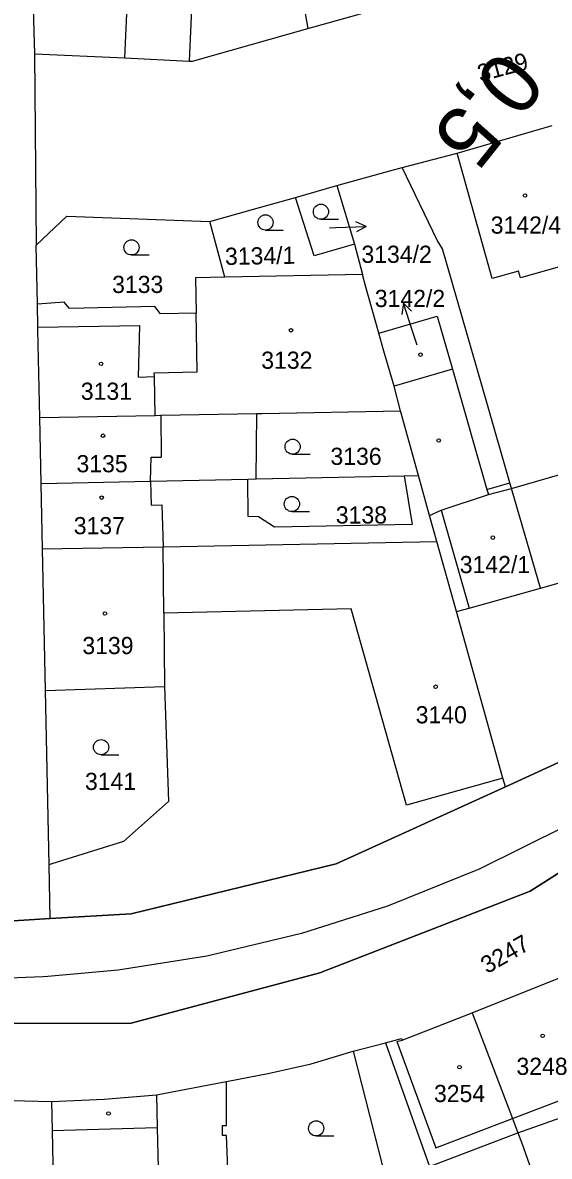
# Model space of a CAD drawing. Extents: x -738085 to -734306, y -1122197 to -1119753.
# Drawn here: x -734573.1 to -734521, y -1120242.7 to -1120130.5 of the extents above; entities that cross this region are included whole.
import ezdxf

# ---------------------------------------------------------------- set-up
doc = ezdxf.new("R2010")
doc.units = 0
for name, color, linetype in [('Hranice parcel', 7, 'Continuous'), ('Parcelní čísla', 7, 'Continuous'), ('Pop  PČ popisy', 7, 'Continuous'), ('SŽDC', 7, 'Continuous'), ('Vnitřní kresba', 7, 'Continuous'), ('Vrstva 1', 7, 'Continuous'), ('Vrstva 53', 7, 'Continuous'), ('Vrstva 7', 7, 'Continuous'), ('Značky budov', 7, 'Continuous'), ('Značky kultur', 7, 'Continuous')]:
    doc.layers.add(name, color=color, linetype=linetype)

msp = doc.modelspace()

# ---------------------------------------------------------------- linework, layer by layer
at = {"layer": 'Hranice parcel'}
for p, q in [((-734572.41, -1120116.59), (-734571.92, -1120133.6)), ((-734544.9, -1120131.12), (-734535.22, -1120128.39)), ((-734571.92, -1120133.6), (-734562.98, -1120134.02)), ((-734571.92, -1120133.6), (-734571.73, -1120152.55)), ((-734562.98, -1120134.02), (-734556.63, -1120134.32)), ((-734530.15, -1120143.44), (-734520.74, -1120140.71)), ((-734535.59, -1120144.87), (-734530.15, -1120143.44)), ((-734546.13, -1120147.81), (-734542.02, -1120146.64)), ((-734542.02, -1120146.64), (-734540.3, -1120152.44)), ((-734553.11, -1120155.71), (-734554.58, -1120150.21)), ((-734571.62, -1120158.37), (-734571.73, -1120152.55)), ((-734540.3, -1120152.44), (-734539.5, -1120155.45)), ((-734539.5, -1120155.45), (-734553.11, -1120155.71)), ((-734535.73, -1120168.92), (-734536.38, -1120166.48)), ((-734571.38, -1120169.6), (-734559.98, -1120169.38)), ((-734571.25, -1120176.11), (-734571.38, -1120169.6)), ((-734550.01, -1120175.67), (-734549.95, -1120169.19)), ((-734533.96, -1120175.34), (-734535.73, -1120168.92)), ((-734550.01, -1120175.67), (-734535.36, -1120175.37)), ((-734535.36, -1120175.37), (-734533.96, -1120175.34)), ((-734571.11, -1120182.59), (-734571.25, -1120176.11)), ((-734550.84, -1120175.69), (-734550.01, -1120175.67)), ((-734559.21, -1120182.39), (-734532.14, -1120181.86)), ((-734530.2, -1120188.8), (-734532.14, -1120181.86)), ((-734571.11, -1120182.59), (-734559.21, -1120182.39)), ((-734570.82, -1120196.6), (-734571.11, -1120182.59)), ((-734525.61, -1120205.26), (-734530.2, -1120188.8)), ((-734570.46, -1120213.84), (-734570.82, -1120196.6)), ((-734525.37, -1120206.12), (-734525.61, -1120205.26)), ((-734570.35, -1120219.16), (-734570.46, -1120213.84)), ((-734585.49, -1120220.06), (-734570.35, -1120219.16)), ((-734540.41, -1120232.29), (-734537.22, -1120231.46)), ((-734540.41, -1120232.29), (-734536.34, -1120248.22)), ((-734581.9, -1120236.98), (-734570.24, -1120237.27))]:
    msp.add_line(p, q, dxfattribs=at)
for points in [[(-734572.41, -1120116.59), (-734560.34, -1120116.31), (-734560.35, -1120115), (-734558.85, -1120114.99), (-734558.79, -1120111.41), (-734558.59, -1120111.41), (-734558.74, -1120099.45), (-734554.13, -1120095.73), (-734547.23, -1120097.18), (-734547.39, -1120099.61), (-734547.17, -1120101.76), (-734544.66, -1120115.52), (-734547.56, -1120116.06), (-734544.9, -1120131.12)], [(-734443.58, -1120106.95), (-734449.99, -1120133.29), (-734459.08, -1120154.68), (-734484.08, -1120187.66), (-734500.69, -1120202.26), (-734522.92, -1120216.44), (-734543.71, -1120224.54), (-734562.36, -1120229.51), (-734589.59, -1120229.56), (-734612.32, -1120225.54), (-734626.24, -1120221.38), (-734644.28, -1120218.16), (-734681.74, -1120210.16)], [(-734562.98, -1120134.02), (-734562.66, -1120126.69), (-734556.3, -1120126.92), (-734556.63, -1120134.32)], [(-734556.63, -1120134.32), (-734556.3, -1120134.34), (-734544.9, -1120131.12)], [(-734517.27, -1120153.31), (-734519.95, -1120153.93), (-734519.79, -1120154.61), (-734523.89, -1120155.76), (-734524.07, -1120155.1), (-734526.69, -1120155.84), (-734530.15, -1120143.44)], [(-734542.02, -1120146.64), (-734536.78, -1120145.2), (-734535.59, -1120144.87)], [(-734521.91, -1120186.49), (-734524.76, -1120176.61), (-734524.92, -1120176.06), (-734527.22, -1120168.12), (-734531.6, -1120152.91), (-734532.1, -1120152.04), (-734535.59, -1120144.87)], [(-734554.58, -1120150.21), (-734550.28, -1120148.99), (-734546.13, -1120147.81)], [(-734540.3, -1120152.44), (-734544.28, -1120153.6), (-734546.13, -1120147.81)], [(-734571.73, -1120152.55), (-734568.72, -1120149.67), (-734554.58, -1120150.21)], [(-734553.11, -1120155.71), (-734556, -1120155.77), (-734555.94, -1120159.27)], [(-734537.88, -1120161.23), (-734539.2, -1120156.57), (-734539.5, -1120155.45)], [(-734555.94, -1120159.27), (-734559.45, -1120159.32), (-734560.03, -1120158.61), (-734568.44, -1120158.81), (-734568.99, -1120158.19), (-734571.62, -1120158.37)], [(-734571.38, -1120169.6), (-734571.57, -1120160.87), (-734571.57, -1120160.65), (-734571.62, -1120158.37)], [(-734559.98, -1120169.38), (-734560.06, -1120165.54), (-734560.07, -1120165.18), (-734555.83, -1120165.08), (-734555.94, -1120159.27)], [(-734537.88, -1120161.23), (-734532.1, -1120159.57), (-734530.6, -1120164.82), (-734536.38, -1120166.48)], [(-734536.38, -1120166.48), (-734537.37, -1120163.02), (-734537.88, -1120161.23)], [(-734559.98, -1120169.38), (-734559.42, -1120169.37), (-734549.95, -1120169.19)], [(-734549.95, -1120169.19), (-734549.41, -1120169.18), (-734535.73, -1120168.92)], [(-734535.36, -1120175.37), (-734534.6, -1120180.18), (-734548.18, -1120180.43), (-734549.77, -1120179.41), (-734550.78, -1120179.38), (-734550.84, -1120175.69)], [(-734532.14, -1120181.86), (-734532.86, -1120179.29), (-734533.96, -1120175.34)], [(-734571.25, -1120176.11), (-734560.46, -1120175.89), (-734550.84, -1120175.69)], [(-734521.91, -1120186.49), (-734495.93, -1120179.13), (-734494.83, -1120178.89)], [(-734525.61, -1120205.26), (-734535.15, -1120207.96), (-734540.6, -1120188.51), (-734559.13, -1120188.96), (-734559.21, -1120182.39)], [(-734525.37, -1120206.12), (-734518.89, -1120203.17), (-734499.33, -1120188.83), (-734493.74, -1120182.73)], [(-734530.2, -1120188.8), (-734528.96, -1120188.45), (-734521.91, -1120186.49)], [(-734570.82, -1120196.6), (-734559.05, -1120196.21), (-734558.68, -1120207.57), (-734563.13, -1120211.53), (-734570.21, -1120213.76), (-734570.46, -1120213.84)], [(-734570.35, -1120219.16), (-734562.37, -1120218.68), (-734542.11, -1120213.74), (-734525.37, -1120206.12)], [(-734528.66, -1120228.48), (-734520.03, -1120225.02), (-734520.09, -1120224.86), (-734519.05, -1120224.27)], [(-734524.13, -1120240.37), (-734513.89, -1120236.74), (-734519.05, -1120224.27)], [(-734537.22, -1120231.46), (-734535.63, -1120231.04), (-734535.59, -1120231.21), (-734528.66, -1120228.48)], [(-734528.66, -1120228.48), (-734524.66, -1120238.96), (-734524.13, -1120240.37)], [(-734537.22, -1120231.46), (-734532.88, -1120243.7), (-734524.13, -1120240.37)], [(-734552.93, -1120235.28), (-734548.69, -1120234.47), (-734544.58, -1120233.52), (-734540.41, -1120232.29)], [(-734570.24, -1120237.27), (-734565.01, -1120237.03), (-734559.86, -1120236.6), (-734553.13, -1120235.32), (-734552.93, -1120235.28)], [(-734552.58, -1120249.77), (-734552.93, -1120240.64), (-734553.34, -1120240.64), (-734553.34, -1120239.63), (-734552.93, -1120239.63), (-734552.93, -1120235.28)], [(-734570.24, -1120237.27), (-734570.18, -1120240.13), (-734569.95, -1120250.14)], [(-734524.13, -1120240.37), (-734523.79, -1120241.29), (-734521.21, -1120248.57)]]:
    msp.add_lwpolyline(points, dxfattribs=at)
at = {"layer": 'Pop  PČ popisy'}
for p, q in [((-734542.12, -1120150.79), (-734539.12, -1120150.69)), ((-734539.12, -1120150.69), (-734540.14, -1120150.22)), ((-734539.12, -1120150.69), (-734540.1, -1120151.22)), ((-734542.76, -1120150.81), (-734542.12, -1120150.79)), ((-734535.44, -1120158.29), (-734535.6, -1120159.39)), ((-734534.51, -1120161.14), (-734535.44, -1120158.29)), ((-734535.44, -1120158.29), (-734534.65, -1120159.08)), ((-734534.08, -1120162.44), (-734534.51, -1120161.14))]:
    msp.add_line(p, q, dxfattribs=at)
at = {"layer": 'SŽDC'}
for p, q in [((-734522.92, -1120216.44), (-734500.69, -1120202.26)), ((-734518.89, -1120203.17), (-734525.37, -1120206.12)), ((-734525.37, -1120206.12), (-734542.11, -1120213.74)), ((-734542.11, -1120213.74), (-734562.37, -1120218.68)), ((-734543.71, -1120224.54), (-734522.92, -1120216.44)), ((-734570.35, -1120219.16), (-734585.49, -1120220.06)), ((-734562.37, -1120218.68), (-734570.35, -1120219.16)), ((-734562.36, -1120229.51), (-734543.71, -1120224.54)), ((-734589.59, -1120229.56), (-734562.36, -1120229.51))]:
    msp.add_line(p, q, dxfattribs=at)
at = {"layer": 'Vnitřní kresba'}
for p, q in [((-734571.57, -1120160.65), (-734561.49, -1120160.5)), ((-734561.64, -1120165.6), (-734561.49, -1120160.5)), ((-734530.6, -1120164.82), (-734527.19, -1120176.72)), ((-734561.64, -1120165.6), (-734560.06, -1120165.54)), ((-734559.42, -1120169.37), (-734559.39, -1120173.52)), ((-734524.76, -1120176.61), (-734504.31, -1120170.63)), ((-734560.46, -1120175.89), (-734560.39, -1120173.53)), ((-734560.39, -1120173.53), (-734559.39, -1120173.52)), ((-734560.46, -1120175.89), (-734560.37, -1120178.25)), ((-734527.19, -1120176.72), (-734524.92, -1120176.06)), ((-734531.71, -1120178.77), (-734527.05, -1120177.2)), ((-734527.19, -1120176.72), (-734527.05, -1120177.2)), ((-734527.05, -1120177.2), (-734524.76, -1120176.61)), ((-734560.37, -1120178.25), (-734559.33, -1120178.22)), ((-734559.33, -1120178.22), (-734559.21, -1120182.39)), ((-734532.86, -1120179.29), (-734531.71, -1120178.77)), ((-734531.71, -1120178.77), (-734528.96, -1120188.45)), ((-734559.13, -1120188.96), (-734559.05, -1120196.21)), ((-734536.09, -1120231.32), (-734535.59, -1120231.21)), ((-734536.09, -1120231.32), (-734532.24, -1120241.86)), ((-734559.86, -1120236.6), (-734559.78, -1120239.85)), ((-734524.66, -1120238.96), (-734518.72, -1120236.68)), ((-734532.24, -1120241.86), (-734524.66, -1120238.96)), ((-734570.18, -1120240.13), (-734559.78, -1120239.85)), ((-734559.78, -1120239.85), (-734559.52, -1120250.03))]:
    msp.add_line(p, q, dxfattribs=at)
at = {"layer": 'Vrstva 1'}
msp.add_lwpolyline([(-734457.52, -1120128.68), (-734458.98, -1120134.34), (-734461.74, -1120142.87), (-734465.37, -1120151.8), (-734469.15, -1120159.42), (-734473.78, -1120167.32), (-734478.71, -1120174.52), (-734484.35, -1120181.61), (-734490.79, -1120188.56), (-734497.21, -1120194.54), (-734504.15, -1120200.17), (-734511.58, -1120205.34), (-734519.33, -1120209.98), (-734527.98, -1120214.28), (-734537.01, -1120217.94), (-734545.52, -1120220.65), (-734554.88, -1120222.87), (-734563.63, -1120224.26), (-734570.58, -1120224.9), (-734571.05, -1120224.92), (-734578.72, -1120225.21)], dxfattribs=at)
at = {"layer": 'Vrstva 53'}
for points in [[(-734443.58, -1120106.95), (-734449.97, -1120133.28), (-734459.08, -1120154.68), (-734484.08, -1120187.66), (-734500.69, -1120202.26), (-734522.92, -1120216.44), (-734543.71, -1120224.54), (-734562.36, -1120229.51), (-734589.59, -1120229.56)], [(-734585.49, -1120220.06), (-734570.35, -1120219.16), (-734562.37, -1120218.68), (-734542.11, -1120213.74), (-734518.89, -1120203.17), (-734499.33, -1120188.83), (-734493.74, -1120182.73), (-734483.91, -1120171.99), (-734473.68, -1120156.85), (-734466.2, -1120141.71), (-734474.93, -1120139.44), (-734481.07, -1120131.93), (-734479.71, -1120127.23)]]:
    msp.add_lwpolyline(points, dxfattribs=at)
at = {"layer": 'Značky budov'}
for centre in [(-734523.43, -1120147.62), (-734546.56, -1120160.96), (-734565.33, -1120164.28), (-734533.76, -1120163.37), (-734565.14, -1120171.39), (-734531.96, -1120171.86), (-734565.27, -1120177.52), (-734526.61, -1120181.47), (-734564.95, -1120188.98), (-734532.27, -1120196.23), (-734521.69, -1120230.77), (-734529.9, -1120233.86), (-734564.59, -1120238.45)]:
    msp.add_circle(centre, 0.175, dxfattribs=at)
at = {"layer": 'Značky kultur'}
for p, q in [((-734543.6, -1120149.98), (-734541.85, -1120149.98)), ((-734549.08, -1120151.04), (-734547.33, -1120151.04)), ((-734562.32, -1120153.51), (-734560.57, -1120153.51)), ((-734546.4, -1120173.23), (-734544.65, -1120173.23)), ((-734546.47, -1120178.9), (-734544.72, -1120178.9)), ((-734565.33, -1120202.96), (-734563.58, -1120202.96)), ((-734544.07, -1120240.67), (-734542.32, -1120240.67))]:
    msp.add_line(p, q, dxfattribs=at)
for centre in [(-734543.6, -1120149.23), (-734549.08, -1120150.29), (-734562.32, -1120152.76), (-734546.4, -1120172.48), (-734546.47, -1120178.15), (-734565.33, -1120202.21), (-734544.07, -1120239.92)]:
    msp.add_circle(centre, 0.75, dxfattribs=at)

# ---------------------------------------------------------------- texts
at = {"layer": 'Parcelní čísla'}
for s, rotation, p in [('3129', 15, (-734527.87, -1120136.4)), ('3134/1', 1, (-734553.07, -1120154.5)), ('3247', 30, (-734527.18, -1120224.67))]:
    msp.add_text(s, height=1.7, rotation=rotation, dxfattribs=at).set_placement(p)
for s, p in [('3142/4', (-734526.82, -1120151.4)), ('3134/2', (-734539.6, -1120154.29)), ('3133', (-734564.24, -1120157.27)), ('3142/2', (-734538.28, -1120158.66)), ('3132', (-734549.5, -1120164.77)), ('3131', (-734567.33, -1120167.84)), ('3136', (-734542.66, -1120174.28)), ('3135', (-734567.76, -1120175.01)), ('3138', (-734542.13, -1120180.08)), ('3137', (-734568.03, -1120181.14)), ('3142/1', (-734529.88, -1120184.99)), ('3139', (-734567.18, -1120193)), ('3140', (-734534.24, -1120199.85)), ('3141', (-734566.92, -1120206.44)), ('3248', (-734524.28, -1120234.63)), ('3254', (-734532.43, -1120237.32))]:
    msp.add_text(s, height=1.7, dxfattribs=at).set_placement(p)
at = {"layer": 'Vrstva 7'}
msp.add_text('0,5', height=6, rotation=231.4794, dxfattribs=at).set_placement((-734525.88, -1120132.95))

doc.saveas('drawing.dxf')
